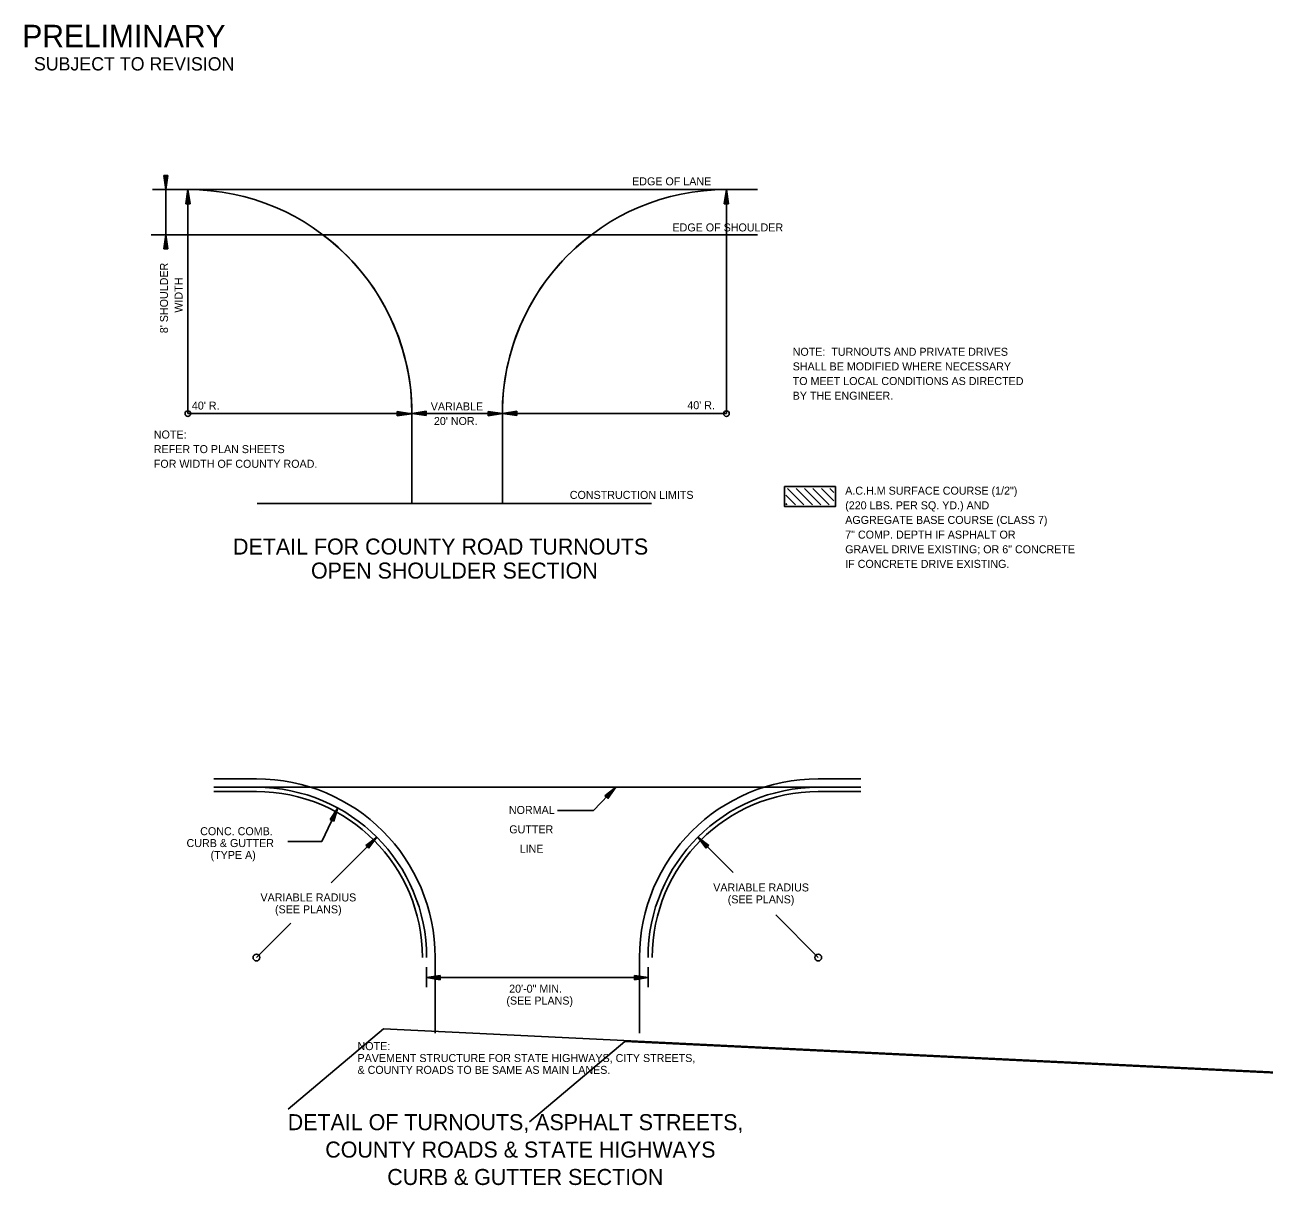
# Model space of a CAD drawing. Extents: x 1227242 to 1227801, y 152460 to 152569.
# Drawn here: x 1227342.92 to 1227362.27, y 152462.05 to 152480.17 of the extents above; entities that cross this region are included whole.
import ezdxf

# ---------------------------------------------------------------- set-up
doc = ezdxf.new("R2010")
doc.units = 0
for name, color, linetype in [('Default', 7, 'Continuous'), ('R_Border Prem', 7, 'Continuous'), ('R_Dimension', 7, 'Continuous')]:
    doc.layers.add(name, color=color, linetype=linetype)

msp = doc.modelspace()

# ---------------------------------------------------------------- linework, layer by layer
at = {"layer": 'Default'}
for p, q in [((1227345.084, 152477.819), (1227345.117, 152477.598)), ((1227345.15, 152477.819), (1227345.084, 152477.819)), ((1227345.089, 152477.819), (1227345.117, 152477.635)), ((1227345.095, 152477.819), (1227345.117, 152477.673)), ((1227345.101, 152477.819), (1227345.117, 152477.71)), ((1227345.106, 152477.819), (1227345.117, 152477.747)), ((1227345.112, 152477.819), (1227345.117, 152477.784)), ((1227345.15, 152477.819), (1227345.117, 152477.598)), ((1227345.128, 152477.819), (1227345.117, 152477.747)), ((1227345.139, 152477.819), (1227345.117, 152477.673)), ((1227345.145, 152477.819), (1227345.117, 152477.635)), ((1227345.133, 152477.819), (1227345.117, 152477.71)), ((1227345.122, 152477.819), (1227345.117, 152477.784)), ((1227344.907, 152477.598), (1227354.356, 152477.598)), ((1227345.117, 152476.892), (1227345.117, 152477.598)), ((1227345.429, 152477.378), (1227345.462, 152477.598)), ((1227345.434, 152477.378), (1227345.462, 152477.561)), ((1227345.439, 152477.378), (1227345.462, 152477.523)), ((1227345.445, 152477.378), (1227345.462, 152477.487)), ((1227345.495, 152477.378), (1227345.462, 152477.598)), ((1227345.462, 152477.598), (1227345.462, 152474.1)), ((1227353.87, 152477.598), (1227345.462, 152477.598)), ((1227345.489, 152477.378), (1227345.462, 152477.561)), ((1227345.484, 152477.378), (1227345.462, 152477.523)), ((1227345.478, 152477.378), (1227345.462, 152477.487)), ((1227348.864, 152477.591), (1227348.867, 152477.6)), ((1227348.867, 152477.597), (1227348.864, 152477.591)), ((1227348.864, 152477.591), (1227348.867, 152477.594)), ((1227353.837, 152477.378), (1227353.87, 152477.598)), ((1227353.842, 152477.378), (1227353.87, 152477.561)), ((1227353.848, 152477.378), (1227353.87, 152477.523)), ((1227353.853, 152477.378), (1227353.87, 152477.486)), ((1227353.903, 152477.378), (1227353.87, 152477.598)), ((1227353.87, 152474.1), (1227353.87, 152477.598)), ((1227353.897, 152477.378), (1227353.87, 152477.561)), ((1227353.892, 152477.378), (1227353.87, 152477.523)), ((1227353.886, 152477.378), (1227353.87, 152477.486)), ((1227345.429, 152477.378), (1227345.495, 152477.378)), ((1227345.451, 152477.378), (1227345.462, 152477.449)), ((1227345.456, 152477.378), (1227345.462, 152477.412)), ((1227345.473, 152477.378), (1227345.462, 152477.449)), ((1227345.467, 152477.378), (1227345.462, 152477.412)), ((1227353.837, 152477.378), (1227353.903, 152477.378)), ((1227353.859, 152477.378), (1227353.87, 152477.449)), ((1227353.864, 152477.378), (1227353.87, 152477.412)), ((1227353.881, 152477.378), (1227353.87, 152477.449)), ((1227353.875, 152477.378), (1227353.87, 152477.412)), ((1227344.888, 152476.892), (1227354.356, 152476.892)), ((1227345.084, 152476.671), (1227345.117, 152476.892)), ((1227345.15, 152476.671), (1227345.117, 152476.892)), ((1227351.762, 152476.892), (1227347.569, 152476.892)), ((1227345.089, 152476.671), (1227345.117, 152476.855)), ((1227345.095, 152476.671), (1227345.117, 152476.817)), ((1227345.1, 152476.671), (1227345.117, 152476.78)), ((1227345.107, 152476.671), (1227345.117, 152476.743)), ((1227345.112, 152476.671), (1227345.117, 152476.706)), ((1227345.145, 152476.671), (1227345.117, 152476.855)), ((1227345.139, 152476.671), (1227345.117, 152476.817)), ((1227345.133, 152476.671), (1227345.117, 152476.78)), ((1227345.128, 152476.671), (1227345.117, 152476.743)), ((1227345.122, 152476.671), (1227345.117, 152476.706)), ((1227345.084, 152476.671), (1227345.15, 152476.671)), ((1227345.462, 152474.101), (1227348.959, 152474.101)), ((1227348.73, 152474.131), (1227348.951, 152474.099)), ((1227348.73, 152474.131), (1227348.73, 152474.066)), ((1227348.73, 152474.127), (1227348.913, 152474.099)), ((1227348.73, 152474.121), (1227348.876, 152474.099)), ((1227348.73, 152474.115), (1227348.839, 152474.099)), ((1227348.73, 152474.109), (1227348.801, 152474.099)), ((1227348.73, 152474.104), (1227348.765, 152474.099)), ((1227348.73, 152474.066), (1227348.951, 152474.099)), ((1227348.73, 152474.088), (1227348.801, 152474.099)), ((1227348.73, 152474.077), (1227348.876, 152474.099)), ((1227348.73, 152474.071), (1227348.913, 152474.099)), ((1227348.73, 152474.082), (1227348.839, 152474.099)), ((1227348.73, 152474.093), (1227348.765, 152474.099)), ((1227348.96, 152474.101), (1227348.984, 152474.101)), ((1227348.984, 152474.101), (1227348.96, 152474.101)), ((1227348.96, 152474.1), (1227348.96, 152472.698)), ((1227348.96, 152474.1), (1227350.372, 152474.1)), ((1227348.96, 152474.1), (1227350.372, 152474.1)), ((1227348.96, 152474.1), (1227348.96, 152472.698)), ((1227349.183, 152474.137), (1227348.963, 152474.103)), ((1227348.963, 152474.103), (1227349.183, 152474.137)), ((1227348.984, 152474.101), (1227348.963, 152474.104)), ((1227349.183, 152474.071), (1227348.963, 152474.103)), ((1227349.183, 152474.071), (1227348.984, 152474.101)), ((1227349.183, 152474.131), (1227349, 152474.103)), ((1227349.183, 152474.076), (1227349, 152474.103)), ((1227349.183, 152474.126), (1227349.038, 152474.103)), ((1227349.183, 152474.082), (1227349.038, 152474.103)), ((1227349.183, 152474.12), (1227349.074, 152474.103)), ((1227349.183, 152474.087), (1227349.074, 152474.103)), ((1227349.183, 152474.115), (1227349.112, 152474.103)), ((1227349.183, 152474.093), (1227349.112, 152474.103)), ((1227349.183, 152474.109), (1227349.148, 152474.103)), ((1227349.183, 152474.098), (1227349.148, 152474.103)), ((1227349.183, 152474.071), (1227349.183, 152474.137)), ((1227349.183, 152474.137), (1227349.183, 152474.101)), ((1227349.183, 152474.101), (1227350.151, 152474.101)), ((1227350.151, 152474.101), (1227349.183, 152474.101)), ((1227349.183, 152474.101), (1227349.183, 152474.071)), ((1227350.151, 152474.133), (1227350.372, 152474.1)), ((1227350.151, 152474.133), (1227350.151, 152474.067)), ((1227350.151, 152474.101), (1227350.151, 152474.133)), ((1227350.151, 152474.133), (1227350.372, 152474.1)), ((1227350.151, 152474.128), (1227350.335, 152474.1)), ((1227350.151, 152474.122), (1227350.297, 152474.1)), ((1227350.151, 152474.116), (1227350.26, 152474.1)), ((1227350.151, 152474.111), (1227350.223, 152474.1)), ((1227350.151, 152474.105), (1227350.186, 152474.1)), ((1227350.151, 152474.067), (1227350.151, 152474.101)), ((1227350.151, 152474.067), (1227350.372, 152474.1)), ((1227350.151, 152474.089), (1227350.223, 152474.1)), ((1227350.151, 152474.078), (1227350.297, 152474.1)), ((1227350.151, 152474.072), (1227350.335, 152474.1)), ((1227350.151, 152474.084), (1227350.26, 152474.1)), ((1227350.151, 152474.095), (1227350.186, 152474.1)), ((1227350.372, 152474.1), (1227350.151, 152474.067)), ((1227350.372, 152474.101), (1227353.87, 152474.101)), ((1227350.372, 152472.698), (1227350.372, 152474.1)), ((1227350.372, 152472.698), (1227350.372, 152474.1)), ((1227350.596, 152474.137), (1227350.375, 152474.103)), ((1227350.596, 152474.071), (1227350.375, 152474.103)), ((1227350.596, 152474.131), (1227350.412, 152474.103)), ((1227350.596, 152474.076), (1227350.412, 152474.103)), ((1227350.596, 152474.126), (1227350.45, 152474.103)), ((1227350.596, 152474.082), (1227350.45, 152474.103)), ((1227350.596, 152474.12), (1227350.486, 152474.103)), ((1227350.596, 152474.087), (1227350.486, 152474.103)), ((1227350.596, 152474.115), (1227350.524, 152474.103)), ((1227350.596, 152474.093), (1227350.524, 152474.103)), ((1227350.596, 152474.109), (1227350.561, 152474.103)), ((1227350.596, 152474.098), (1227350.561, 152474.103)), ((1227350.596, 152474.071), (1227350.596, 152474.137)), ((1227346.543, 152472.698), (1227352.701, 152472.698)), ((1227348.96, 152472.698), (1227350.372, 152472.698)), ((1227346.532, 152468.398), (1227345.867, 152468.398)), ((1227355.304, 152468.398), (1227355.969, 152468.398)), ((1227350.918, 152468.265), (1227345.867, 152468.265)), ((1227346.532, 152468.199), (1227345.867, 152468.199)), ((1227350.918, 152468.265), (1227355.969, 152468.265)), ((1227351.796, 152467.901), (1227352.142, 152468.265)), ((1227351.972, 152468.133), (1227352.142, 152468.265)), ((1227351.976, 152468.129), (1227352.117, 152468.239)), ((1227351.98, 152468.125), (1227352.092, 152468.213)), ((1227351.984, 152468.121), (1227352.068, 152468.187)), ((1227352.007, 152468.1), (1227352.068, 152468.187)), ((1227352.011, 152468.096), (1227352.092, 152468.213)), ((1227352.014, 152468.092), (1227352.117, 152468.239)), ((1227352.018, 152468.089), (1227352.142, 152468.265)), ((1227355.304, 152468.199), (1227355.969, 152468.199)), ((1227351.972, 152468.133), (1227352.018, 152468.089)), ((1227351.988, 152468.118), (1227352.043, 152468.161)), ((1227351.992, 152468.114), (1227352.018, 152468.136)), ((1227351.999, 152468.107), (1227352.018, 152468.136)), ((1227352.003, 152468.103), (1227352.043, 152468.161)), ((1227347.555, 152467.42), (1227347.802, 152467.942)), ((1227347.682, 152467.763), (1227347.802, 152467.942)), ((1227347.687, 152467.761), (1227347.786, 152467.91)), ((1227347.691, 152467.759), (1227347.771, 152467.876)), ((1227347.696, 152467.757), (1227347.756, 152467.845)), ((1227347.702, 152467.755), (1227347.74, 152467.812)), ((1227347.706, 152467.751), (1227347.725, 152467.78)), ((1227347.715, 152467.747), (1227347.725, 152467.78)), ((1227347.721, 152467.745), (1227347.74, 152467.812)), ((1227347.725, 152467.743), (1227347.756, 152467.845)), ((1227347.73, 152467.74), (1227347.771, 152467.876)), ((1227347.735, 152467.738), (1227347.786, 152467.91)), ((1227347.74, 152467.736), (1227347.802, 152467.942)), ((1227351.231, 152467.901), (1227351.796, 152467.901)), ((1227347.682, 152467.763), (1227347.74, 152467.736)), ((1227347.025, 152467.42), (1227347.555, 152467.42)), ((1227347.699, 152466.774), (1227348.412, 152467.486)), ((1227348.238, 152467.358), (1227348.411, 152467.486)), ((1227348.242, 152467.355), (1227348.387, 152467.461)), ((1227348.246, 152467.351), (1227348.361, 152467.435)), ((1227348.25, 152467.347), (1227348.335, 152467.41)), ((1227348.271, 152467.325), (1227348.335, 152467.41)), ((1227348.276, 152467.321), (1227348.361, 152467.435)), ((1227348.28, 152467.317), (1227348.387, 152467.461)), ((1227348.283, 152467.313), (1227348.411, 152467.486)), ((1227353.553, 152467.313), (1227353.425, 152467.486)), ((1227353.598, 152467.358), (1227353.425, 152467.486)), ((1227353.974, 152466.936), (1227353.425, 152467.486)), ((1227353.556, 152467.317), (1227353.45, 152467.461)), ((1227353.594, 152467.355), (1227353.45, 152467.461)), ((1227353.589, 152467.351), (1227353.476, 152467.435)), ((1227353.56, 152467.321), (1227353.476, 152467.435)), ((1227353.564, 152467.325), (1227353.501, 152467.41)), ((1227353.586, 152467.347), (1227353.501, 152467.41)), ((1227348.238, 152467.358), (1227348.283, 152467.313)), ((1227348.254, 152467.343), (1227348.31, 152467.385)), ((1227348.257, 152467.34), (1227348.285, 152467.36)), ((1227348.265, 152467.332), (1227348.285, 152467.36)), ((1227348.268, 152467.329), (1227348.31, 152467.385)), ((1227353.583, 152467.343), (1227353.526, 152467.385)), ((1227353.568, 152467.329), (1227353.526, 152467.385)), ((1227353.578, 152467.34), (1227353.551, 152467.36)), ((1227353.572, 152467.332), (1227353.551, 152467.36)), ((1227353.553, 152467.313), (1227353.598, 152467.358)), ((1227355.305, 152465.606), (1227354.64, 152466.271)), ((1227346.532, 152465.606), (1227347.069, 152466.144)), ((1227349.323, 152464.426), (1227349.323, 152465.606)), ((1227352.513, 152464.426), (1227352.513, 152465.606)), ((1227349.19, 152465.141), (1227349.19, 152465.456)), ((1227349.403, 152465.324), (1227349.19, 152465.293)), ((1227352.646, 152465.293), (1227349.19, 152465.293)), ((1227349.403, 152465.26), (1227349.19, 152465.293)), ((1227349.403, 152465.319), (1227349.226, 152465.293)), ((1227349.403, 152465.266), (1227349.226, 152465.293)), ((1227349.403, 152465.313), (1227349.262, 152465.293)), ((1227349.403, 152465.271), (1227349.262, 152465.293)), ((1227349.403, 152465.308), (1227349.298, 152465.293)), ((1227349.403, 152465.277), (1227349.298, 152465.293)), ((1227349.403, 152465.302), (1227349.333, 152465.293)), ((1227349.403, 152465.282), (1227349.333, 152465.293)), ((1227349.403, 152465.298), (1227349.369, 152465.293)), ((1227349.403, 152465.287), (1227349.369, 152465.293)), ((1227349.403, 152465.26), (1227349.403, 152465.324)), ((1227352.433, 152465.324), (1227352.646, 152465.293)), ((1227352.433, 152465.324), (1227352.433, 152465.26)), ((1227352.433, 152465.319), (1227352.611, 152465.293)), ((1227352.433, 152465.313), (1227352.574, 152465.293)), ((1227352.433, 152465.308), (1227352.539, 152465.293)), ((1227352.433, 152465.302), (1227352.503, 152465.293)), ((1227352.433, 152465.298), (1227352.467, 152465.293)), ((1227352.433, 152465.26), (1227352.646, 152465.293)), ((1227352.433, 152465.282), (1227352.503, 152465.293)), ((1227352.433, 152465.271), (1227352.574, 152465.293)), ((1227352.433, 152465.266), (1227352.611, 152465.293)), ((1227352.433, 152465.277), (1227352.539, 152465.293)), ((1227352.433, 152465.287), (1227352.467, 152465.293)), ((1227352.646, 152465.141), (1227352.646, 152465.456))]:
    msp.add_line(p, q, dxfattribs=at)
msp.add_lwpolyline([(1227354.779, 152472.96), (1227354.779, 152472.648), (1227355.573, 152472.648), (1227355.573, 152472.96)], close=True, dxfattribs=at)
for points in [[(1227354.798, 152472.826), (1227354.948, 152472.677)], [(1227354.826, 152472.931), (1227355.08, 152472.677)], [(1227354.958, 152472.931), (1227355.212, 152472.677)], [(1227355.09, 152472.931), (1227355.344, 152472.677)], [(1227355.222, 152472.931), (1227355.476, 152472.677)], [(1227355.354, 152472.931), (1227355.548, 152472.737)], [(1227355.486, 152472.931), (1227355.548, 152472.869)], [(1227354.798, 152472.694), (1227354.816, 152472.677)]]:
    msp.add_lwpolyline(points, dxfattribs=at)
for centre, radius in [((1227345.462, 152474.1), 0.0441), ((1227353.87, 152474.1), 0.0441), ((1227346.532, 152465.606), 0.0532), ((1227355.304, 152465.606), 0.0532)]:
    msp.add_circle(centre, radius, dxfattribs=at)
for centre, radius, start, end in [((1227345.462, 152474.101), 3.498, 0, 90), ((1227345.462, 152474.101), 3.498, 0, 90), ((1227353.87, 152474.101), 3.498, 90, 180), ((1227353.87, 152474.101), 3.498, 90, 180), ((1227345.462, 152474.101), 3.498, 0.0007, 52.9538), ((1227353.87, 152474.101), 3.498, 127.0464, 180), ((1227346.532, 152465.606), 2.791, 0, 90), ((1227355.304, 152465.606), 2.791, 90, 180), ((1227346.532, 152465.606), 2.658, 0, 90), ((1227346.532, 152465.606), 2.592, 0, 90), ((1227355.304, 152465.606), 2.658, 90, 180), ((1227355.304, 152465.606), 2.592, 90, 179.9971)]:
    msp.add_arc(centre, radius, start, end, dxfattribs=at)
at = {"layer": 'R_Dimension'}
for p, q in [((1227348.514, 152464.494), (1227347.029, 152463.239)), ((1227352.283, 152464.294), (1227350.798, 152463.039))]:
    msp.add_line(p, q, dxfattribs=at)
for points in [[(1227391.101, 152464.336), (1227380.479, 152462.94), (1227348.514, 152464.494)], [(1227394.87, 152464.137), (1227384.248, 152462.741), (1227352.283, 152464.294)]]:
    msp.add_lwpolyline(points, dxfattribs=at)

# ---------------------------------------------------------------- texts
at = {"layer": 'Default'}
for s, height, p in [('EDGE OF LANE', 0.125, (1227352.398, 152477.665)), ('EDGE OF SHOULDER', 0.125, (1227353.028, 152476.945)), ('NOTE:  TURNOUTS AND PRIVATE DRIVES', 0.125, (1227354.905, 152475.003)), ('SHALL BE MODIFIED WHERE NECESSARY', 0.125, (1227354.905, 152474.775)), ('TO MEET LOCAL CONDITIONS AS DIRECTED', 0.125, (1227354.905, 152474.546)), ('BY THE ENGINEER.', 0.125, (1227354.905, 152474.317)), ("40' R.", 0.125, (1227345.524, 152474.163)), ('VARIABLE', 0.125, (1227349.254, 152474.15)), ("40' R.", 0.125, (1227353.26, 152474.169)), ("20' NOR.", 0.125, (1227349.303, 152473.922)), ('NOTE:', 0.125, (1227344.93, 152473.711)), ('REFER TO PLAN SHEETS', 0.125, (1227344.93, 152473.483)), ('FOR WIDTH OF COUNTY ROAD.', 0.125, (1227344.93, 152473.254)), ('CONSTRUCTION LIMITS', 0.125, (1227351.425, 152472.768)), ('A.C.H.M SURFACE COURSE (1/2") ', 0.125, (1227355.725, 152472.834)), ('(220 LBS. PER SQ. YD.) AND ', 0.125, (1227355.725, 152472.605)), ('AGGREGATE BASE COURSE (CLASS 7)', 0.125, (1227355.725, 152472.377)), ('7" COMP. DEPTH IF ASPHALT OR', 0.125, (1227355.725, 152472.148)), ('DETAIL FOR COUNTY ROAD TURNOUTS', 0.25, (1227346.167, 152471.899)), ('GRAVEL DRIVE EXISTING; OR 6" CONCRETE', 0.125, (1227355.725, 152471.919)), ('OPEN SHOULDER SECTION', 0.25, (1227347.384, 152471.524)), ('IF CONCRETE DRIVE EXISTING.', 0.125, (1227355.725, 152471.691)), ('NORMAL', 0.125, (1227350.474, 152467.848)), ('CONC. COMB.', 0.125, (1227345.654, 152467.516)), ('GUTTER', 0.125, (1227350.48, 152467.545)), ('CURB & GUTTER', 0.125, (1227345.441, 152467.331)), ('(TYPE A)', 0.125, (1227345.816, 152467.145)), ('LINE', 0.125, (1227350.642, 152467.242)), ('VARIABLE RADIUS', 0.125, (1227353.664, 152466.638)), ('VARIABLE RADIUS', 0.125, (1227346.595, 152466.482)), ('(SEE PLANS)', 0.125, (1227346.822, 152466.296)), ('(SEE PLANS)', 0.125, (1227353.891, 152466.452)), ('20\'-0" MIN.', 0.125, (1227350.478, 152465.057)), ('(SEE PLANS)', 0.125, (1227350.435, 152464.871)), ('NOTE:', 0.125, (1227348.11, 152464.16)), ('& COUNTY ROADS TO BE SAME AS MAIN LANES.', 0.125, (1227348.11, 152463.789)), ('PAVEMENT STRUCTURE FOR STATE HIGHWAYS, CITY STREETS,', 0.125, (1227348.11, 152463.974)), ('DETAIL OF TURNOUTS, ASPHALT STREETS, ', 0.25, (1227347.021, 152462.91)), ('COUNTY ROADS & STATE HIGHWAYS', 0.25, (1227347.607, 152462.482)), ('CURB & GUTTER SECTION', 0.25, (1227348.575, 152462.054))]:
    msp.add_text(s, height=height, dxfattribs=at).set_placement(p)
for s, p in [("8' SHOULDER", (1227345.151, 152475.356)), ('WIDTH', (1227345.379, 152475.676))]:
    msp.add_text(s, height=0.125, rotation=90, dxfattribs=at).set_placement(p)
at = {"layer": 'R_Border Prem'}
for s, height, p in [('PRELIMINARY', 0.35, (1227342.877, 152479.822)), ('SUBJECT TO REVISION', 0.20751, (1227343.058, 152479.459))]:
    msp.add_text(s, height=height, rotation=359.9809, dxfattribs=at).set_placement(p)

doc.saveas('drawing.dxf')
